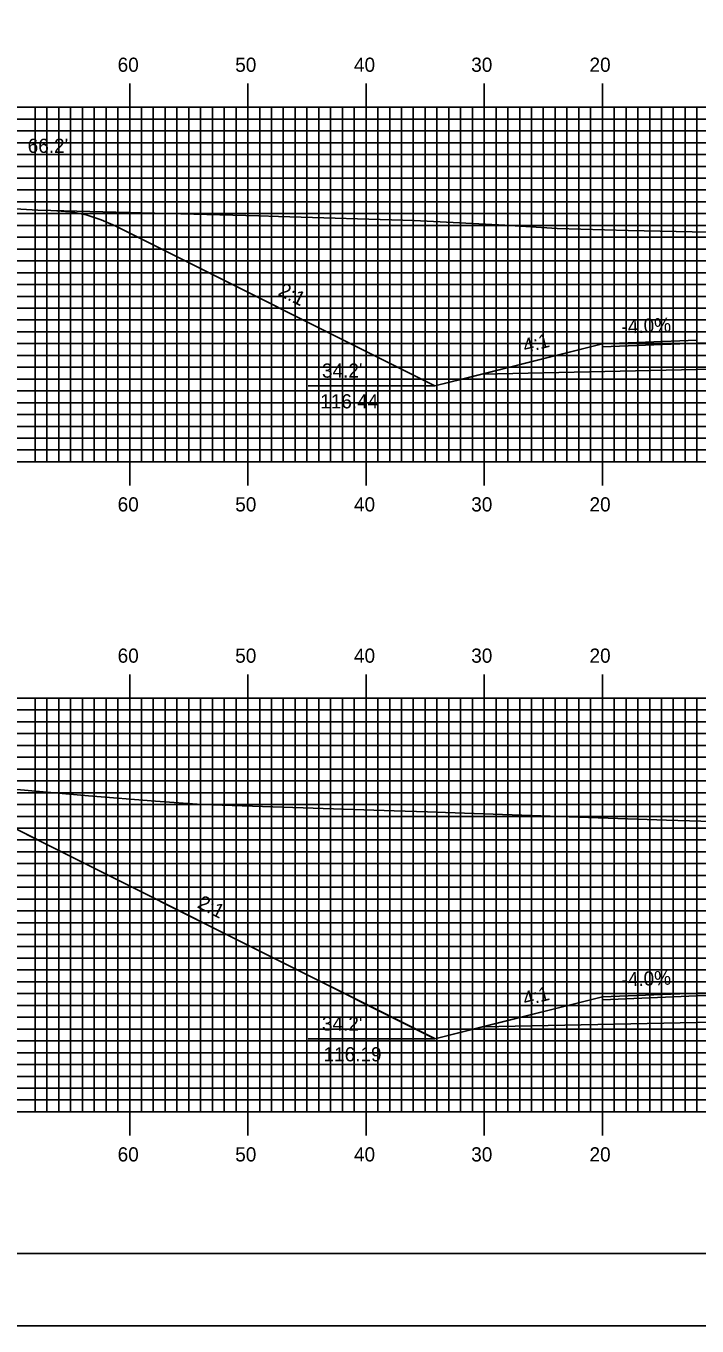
# Model space of a CAD drawing. Extents: x 1770842 to 1771185, y 442591 to 442811.
# Drawn here: x 1770938.8 to 1770995.6, y 442590.5 to 442700.5 of the extents above; entities that cross this region are included whole.
import ezdxf

# ---------------------------------------------------------------- set-up
doc = ezdxf.new("R2010")
doc.units = 0
for name, color, linetype in [('ANNOTATION', 7, 'Continuous'), ('BORDER', 7, 'Continuous'), ('D_Roadway_Centerline', 7, 'Continuous'), ('D_Roadway_Edge_Shoulder', 7, 'Continuous'), ('D_Roadway_SlopeLines', 7, 'Continuous'), ('D_Roadway_SubGrade', 7, 'Continuous'), ('D_Text_Standard', 7, 'Continuous'), ('H_V ANNOTATION', 7, 'Continuous'), ('MAJOR', 7, 'Continuous'), ('MINOR', 7, 'Continuous'), ('PDRAIN', 7, 'Continuous'), ('PLOT BOUNDARY', 7, 'Continuous'), ('S_Roadway_Centerline', 7, 'Continuous')]:
    doc.layers.add(name, color=color, linetype=linetype)

msp = doc.modelspace()

# ---------------------------------------------------------------- linework, layer by layer
at = {"layer": 'BORDER'}
msp.add_lwpolyline([(1770857.95, 442596.67), (1771177.95, 442596.67), (1771177.95, 442806.67), (1770857.95, 442806.67)], close=True, dxfattribs=at)
at = {"layer": 'D_Roadway_Centerline'}
for points in [[(1770941.38, 442684.91), (1770942.49, 442684.82), (1770942.63, 442684.81), (1770942.88, 442684.76), (1770943.88, 442684.56), (1770944.45, 442684.37), (1770945.13, 442684.15), (1770946.32, 442683.63), (1770946.38, 442683.6), (1770946.82, 442683.38), (1770973.38, 442670.1), (1770975.79, 442670.7), (1770977.38, 442671.1), (1770987.55, 442673.65), (1770995.55, 442673.97)], [(1770928.14, 442636.32), (1770928.6, 442636.27), (1770929.39, 442636.2), (1770930.36, 442635.99), (1770930.64, 442635.93), (1770931.48, 442635.66), (1770931.89, 442635.53), (1770933.14, 442634.97), (1770933.14, 442634.97), (1770955.81, 442623.64), (1770973.37, 442614.86), (1770973.38, 442614.85), (1770977.38, 442615.85), (1770977.38, 442615.85), (1770987.55, 442618.4), (1770995.55, 442618.72), (1771007.55, 442618.96), (1771019.55, 442618.72), (1771027.55, 442618.4), (1771027.55, 442618.4), (1771037.73, 442615.85), (1771041.73, 442614.85), (1771041.74, 442614.86), (1771068.97, 442628.47)]]:
    msp.add_lwpolyline(points, dxfattribs=at)
at = {"layer": 'D_Roadway_Edge_Shoulder'}
for points in [[(1770995.55, 442673.97), (1770987.55, 442673.65), (1770987.55, 442673.4), (1770995.55, 442673.72)], [(1770995.55, 442618.72), (1770987.55, 442618.4), (1770987.55, 442618.15), (1770995.55, 442618.47)]]:
    msp.add_lwpolyline(points, close=True, dxfattribs=at)
at = {"layer": 'D_Roadway_SlopeLines'}
for points in [[(1770973.38, 442670.1), (1770946.38, 442683.6), (1770945.13, 442684.15), (1770943.88, 442684.56), (1770942.63, 442684.81), (1770941.38, 442684.91)], [(1770987.55, 442673.65), (1770973.38, 442670.1)], [(1770973.38, 442614.85), (1770933.14, 442634.97), (1770931.89, 442635.53), (1770930.64, 442635.93), (1770929.39, 442636.2), (1770928.14, 442636.32)], [(1770987.55, 442618.4), (1770973.38, 442614.85)]]:
    msp.add_lwpolyline(points, dxfattribs=at)
at = {"layer": 'D_Roadway_SubGrade'}
for points in [[(1770995.55, 442671.47), (1770977.38, 442671.1), (1770987.55, 442673.65), (1770987.55, 442673.4), (1770995.55, 442673.72), (1771007.55, 442673.96), (1771019.55, 442673.72), (1771027.55, 442673.4), (1771027.55, 442673.65), (1771037.73, 442671.1), (1771019.55, 442671.47), (1771007.55, 442671.71)], [(1770995.55, 442616.22), (1770977.38, 442615.85), (1770987.55, 442618.4), (1770987.55, 442618.15), (1770995.55, 442618.47), (1771007.55, 442618.71), (1771019.55, 442618.47), (1771027.55, 442618.15), (1771027.55, 442618.4), (1771037.73, 442615.85), (1771019.55, 442616.22), (1771007.55, 442616.46)]]:
    msp.add_lwpolyline(points, close=True, dxfattribs=at)
at = {"layer": 'MAJOR'}
for p, q in [((1770947.55, 442695.67), (1770947.55, 442693.67)), ((1770957.55, 442695.67), (1770957.55, 442693.67)), ((1770967.55, 442695.67), (1770967.55, 442693.67)), ((1770977.55, 442695.67), (1770977.55, 442693.67)), ((1770987.55, 442695.67), (1770987.55, 442693.67)), ((1770867.55, 442693.67), (1771147.55, 442693.67)), ((1770867.55, 442693.67), (1771147.55, 442693.67)), ((1770947.55, 442663.67), (1770947.55, 442693.67)), ((1770957.55, 442663.67), (1770957.55, 442693.67)), ((1770967.55, 442663.67), (1770967.55, 442693.67)), ((1770977.55, 442663.67), (1770977.55, 442693.67)), ((1770987.55, 442663.67), (1770987.55, 442693.67)), ((1770867.55, 442688.67), (1771147.55, 442688.67)), ((1770867.55, 442683.67), (1771147.55, 442683.67)), ((1770867.55, 442678.67), (1771147.55, 442678.67)), ((1770867.55, 442673.67), (1771147.55, 442673.67)), ((1770867.55, 442668.67), (1771147.55, 442668.67)), ((1770867.55, 442663.67), (1771147.55, 442663.67)), ((1770867.55, 442663.67), (1771147.55, 442663.67)), ((1770947.55, 442661.66), (1770947.55, 442663.67)), ((1770957.55, 442661.66), (1770957.55, 442663.67)), ((1770967.55, 442661.66), (1770967.55, 442663.67)), ((1770977.55, 442661.66), (1770977.55, 442663.67)), ((1770987.55, 442661.66), (1770987.55, 442663.67)), ((1770947.55, 442645.67), (1770947.55, 442643.67)), ((1770957.55, 442645.67), (1770957.55, 442643.67)), ((1770967.55, 442645.67), (1770967.55, 442643.67)), ((1770977.55, 442645.67), (1770977.55, 442643.67)), ((1770987.55, 442645.67), (1770987.55, 442643.67)), ((1770867.55, 442643.67), (1771147.55, 442643.67)), ((1770867.55, 442643.67), (1771147.55, 442643.67)), ((1770947.55, 442608.67), (1770947.55, 442643.67)), ((1770957.55, 442608.67), (1770957.55, 442643.67)), ((1770967.55, 442608.67), (1770967.55, 442643.67)), ((1770977.55, 442608.67), (1770977.55, 442643.67)), ((1770987.55, 442608.67), (1770987.55, 442643.67)), ((1770867.55, 442638.67), (1771147.55, 442638.67)), ((1770867.55, 442633.67), (1771147.55, 442633.67)), ((1770867.55, 442628.67), (1771147.55, 442628.67)), ((1770867.55, 442623.67), (1771147.55, 442623.67)), ((1770867.55, 442618.67), (1771147.55, 442618.67)), ((1770867.55, 442613.67), (1771147.55, 442613.67)), ((1770867.55, 442608.67), (1771147.55, 442608.67)), ((1770867.55, 442608.67), (1771147.55, 442608.67)), ((1770947.55, 442606.66), (1770947.55, 442608.67)), ((1770957.55, 442606.66), (1770957.55, 442608.67)), ((1770967.55, 442606.66), (1770967.55, 442608.67)), ((1770977.55, 442606.66), (1770977.55, 442608.67)), ((1770987.55, 442606.66), (1770987.55, 442608.67))]:
    msp.add_line(p, q, dxfattribs=at)
at = {"layer": 'MINOR'}
for p, q in [((1770939.55, 442663.67), (1770939.55, 442693.67)), ((1770940.55, 442663.67), (1770940.55, 442693.67)), ((1770941.55, 442663.67), (1770941.55, 442693.67)), ((1770942.55, 442663.67), (1770942.55, 442693.67)), ((1770943.55, 442663.67), (1770943.55, 442693.67)), ((1770944.55, 442663.67), (1770944.55, 442693.67)), ((1770945.55, 442663.67), (1770945.55, 442693.67)), ((1770946.55, 442663.67), (1770946.55, 442693.67)), ((1770948.55, 442663.67), (1770948.55, 442693.67)), ((1770949.55, 442663.67), (1770949.55, 442693.67)), ((1770950.55, 442663.67), (1770950.55, 442693.67)), ((1770951.55, 442663.67), (1770951.55, 442693.67)), ((1770952.55, 442663.67), (1770952.55, 442693.67)), ((1770953.55, 442663.67), (1770953.55, 442693.67)), ((1770954.55, 442663.67), (1770954.55, 442693.67)), ((1770955.55, 442663.67), (1770955.55, 442693.67)), ((1770956.55, 442663.67), (1770956.55, 442693.67)), ((1770958.55, 442663.67), (1770958.55, 442693.67)), ((1770959.55, 442663.67), (1770959.55, 442693.67)), ((1770960.55, 442663.67), (1770960.55, 442693.67)), ((1770961.55, 442663.67), (1770961.55, 442693.67)), ((1770962.55, 442663.67), (1770962.55, 442693.67)), ((1770963.55, 442663.67), (1770963.55, 442693.67)), ((1770964.55, 442663.67), (1770964.55, 442693.67)), ((1770965.55, 442663.67), (1770965.55, 442693.67)), ((1770966.55, 442663.67), (1770966.55, 442693.67)), ((1770968.55, 442663.67), (1770968.55, 442693.67)), ((1770969.55, 442663.67), (1770969.55, 442693.67)), ((1770970.55, 442663.67), (1770970.55, 442693.67)), ((1770971.55, 442663.67), (1770971.55, 442693.67)), ((1770972.55, 442663.67), (1770972.55, 442693.67)), ((1770973.55, 442663.67), (1770973.55, 442693.67)), ((1770974.55, 442663.67), (1770974.55, 442693.67)), ((1770975.55, 442663.67), (1770975.55, 442693.67)), ((1770976.55, 442663.67), (1770976.55, 442693.67)), ((1770978.55, 442663.67), (1770978.55, 442693.67)), ((1770979.55, 442663.67), (1770979.55, 442693.67)), ((1770980.55, 442663.67), (1770980.55, 442693.67)), ((1770981.55, 442663.67), (1770981.55, 442693.67)), ((1770982.55, 442663.67), (1770982.55, 442693.67)), ((1770983.55, 442663.67), (1770983.55, 442693.67)), ((1770984.55, 442663.67), (1770984.55, 442693.67)), ((1770985.55, 442663.67), (1770985.55, 442693.67)), ((1770986.55, 442663.67), (1770986.55, 442693.67)), ((1770988.55, 442663.67), (1770988.55, 442693.67)), ((1770989.55, 442663.67), (1770989.55, 442693.67)), ((1770990.55, 442663.67), (1770990.55, 442693.67)), ((1770991.55, 442663.67), (1770991.55, 442693.67)), ((1770992.55, 442663.67), (1770992.55, 442693.67)), ((1770993.55, 442663.67), (1770993.55, 442693.67)), ((1770994.55, 442663.67), (1770994.55, 442693.67)), ((1770995.55, 442663.67), (1770995.55, 442693.67)), ((1770867.55, 442692.67), (1771147.55, 442692.67)), ((1770867.55, 442691.67), (1771147.55, 442691.67)), ((1770867.55, 442690.67), (1771147.55, 442690.67)), ((1770867.55, 442689.67), (1771147.55, 442689.67)), ((1770867.55, 442687.67), (1771147.55, 442687.67)), ((1770867.55, 442686.67), (1771147.55, 442686.67)), ((1770867.55, 442685.67), (1771147.55, 442685.67)), ((1770867.55, 442684.67), (1771147.55, 442684.67)), ((1770867.55, 442682.67), (1771147.55, 442682.67)), ((1770867.55, 442681.67), (1771147.55, 442681.67)), ((1770867.55, 442680.67), (1771147.55, 442680.67)), ((1770867.55, 442679.67), (1771147.55, 442679.67)), ((1770867.55, 442677.67), (1771147.55, 442677.67)), ((1770867.55, 442676.67), (1771147.55, 442676.67)), ((1770867.55, 442675.67), (1771147.55, 442675.67)), ((1770867.55, 442674.67), (1771147.55, 442674.67)), ((1770867.55, 442672.67), (1771147.55, 442672.67)), ((1770867.55, 442671.67), (1771147.55, 442671.67)), ((1770867.55, 442670.67), (1771147.55, 442670.67)), ((1770867.55, 442669.67), (1771147.55, 442669.67)), ((1770867.55, 442667.67), (1771147.55, 442667.67)), ((1770867.55, 442666.67), (1771147.55, 442666.67)), ((1770867.55, 442665.67), (1771147.55, 442665.67)), ((1770867.55, 442664.67), (1771147.55, 442664.67)), ((1770939.55, 442608.67), (1770939.55, 442643.67)), ((1770940.55, 442608.67), (1770940.55, 442643.67)), ((1770941.55, 442608.67), (1770941.55, 442643.67)), ((1770942.55, 442608.67), (1770942.55, 442643.67)), ((1770943.55, 442608.67), (1770943.55, 442643.67)), ((1770944.55, 442608.67), (1770944.55, 442643.67)), ((1770945.55, 442608.67), (1770945.55, 442643.67)), ((1770946.55, 442608.67), (1770946.55, 442643.67)), ((1770948.55, 442608.67), (1770948.55, 442643.67)), ((1770949.55, 442608.67), (1770949.55, 442643.67)), ((1770950.55, 442608.67), (1770950.55, 442643.67)), ((1770951.55, 442608.67), (1770951.55, 442643.67)), ((1770952.55, 442608.67), (1770952.55, 442643.67)), ((1770953.55, 442608.67), (1770953.55, 442643.67)), ((1770954.55, 442608.67), (1770954.55, 442643.67)), ((1770955.55, 442608.67), (1770955.55, 442643.67)), ((1770956.55, 442608.67), (1770956.55, 442643.67)), ((1770958.55, 442608.67), (1770958.55, 442643.67)), ((1770959.55, 442608.67), (1770959.55, 442643.67)), ((1770960.55, 442608.67), (1770960.55, 442643.67)), ((1770961.55, 442608.67), (1770961.55, 442643.67)), ((1770962.55, 442608.67), (1770962.55, 442643.67)), ((1770963.55, 442608.67), (1770963.55, 442643.67)), ((1770964.55, 442608.67), (1770964.55, 442643.67)), ((1770965.55, 442608.67), (1770965.55, 442643.67)), ((1770966.55, 442608.67), (1770966.55, 442643.67)), ((1770968.55, 442608.67), (1770968.55, 442643.67)), ((1770969.55, 442608.67), (1770969.55, 442643.67)), ((1770970.55, 442608.67), (1770970.55, 442643.67)), ((1770971.55, 442608.67), (1770971.55, 442643.67)), ((1770972.55, 442608.67), (1770972.55, 442643.67)), ((1770973.55, 442608.67), (1770973.55, 442643.67)), ((1770974.55, 442608.67), (1770974.55, 442643.67)), ((1770975.55, 442608.67), (1770975.55, 442643.67)), ((1770976.55, 442608.67), (1770976.55, 442643.67)), ((1770978.55, 442608.67), (1770978.55, 442643.67)), ((1770979.55, 442608.67), (1770979.55, 442643.67)), ((1770980.55, 442608.67), (1770980.55, 442643.67)), ((1770981.55, 442608.67), (1770981.55, 442643.67)), ((1770982.55, 442608.67), (1770982.55, 442643.67)), ((1770983.55, 442608.67), (1770983.55, 442643.67)), ((1770984.55, 442608.67), (1770984.55, 442643.67)), ((1770985.55, 442608.67), (1770985.55, 442643.67)), ((1770986.55, 442608.67), (1770986.55, 442643.67)), ((1770988.55, 442608.67), (1770988.55, 442643.67)), ((1770989.55, 442608.67), (1770989.55, 442643.67)), ((1770990.55, 442608.67), (1770990.55, 442643.67)), ((1770991.55, 442608.67), (1770991.55, 442643.67)), ((1770992.55, 442608.67), (1770992.55, 442643.67)), ((1770993.55, 442608.67), (1770993.55, 442643.67)), ((1770994.55, 442608.67), (1770994.55, 442643.67)), ((1770995.55, 442608.67), (1770995.55, 442643.67)), ((1770867.55, 442642.67), (1771147.55, 442642.67)), ((1770867.55, 442641.67), (1771147.55, 442641.67)), ((1770867.55, 442640.67), (1771147.55, 442640.67)), ((1770867.55, 442639.67), (1771147.55, 442639.67)), ((1770867.55, 442637.67), (1771147.55, 442637.67)), ((1770867.55, 442636.67), (1771147.55, 442636.67)), ((1770867.55, 442635.67), (1771147.55, 442635.67)), ((1770867.55, 442634.67), (1771147.55, 442634.67)), ((1770867.55, 442632.67), (1771147.55, 442632.67)), ((1770867.55, 442631.67), (1771147.55, 442631.67)), ((1770867.55, 442630.67), (1771147.55, 442630.67)), ((1770867.55, 442629.67), (1771147.55, 442629.67)), ((1770867.55, 442627.67), (1771147.55, 442627.67)), ((1770867.55, 442626.67), (1771147.55, 442626.67)), ((1770867.55, 442625.67), (1771147.55, 442625.67)), ((1770867.55, 442624.67), (1771147.55, 442624.67)), ((1770867.55, 442622.67), (1771147.55, 442622.67)), ((1770867.55, 442621.67), (1771147.55, 442621.67)), ((1770867.55, 442620.67), (1771147.55, 442620.67)), ((1770867.55, 442619.67), (1771147.55, 442619.67)), ((1770867.55, 442617.67), (1771147.55, 442617.67)), ((1770867.55, 442616.67), (1771147.55, 442616.67)), ((1770867.55, 442615.67), (1771147.55, 442615.67)), ((1770867.55, 442614.67), (1771147.55, 442614.67)), ((1770867.55, 442612.67), (1771147.55, 442612.67)), ((1770867.55, 442611.67), (1771147.55, 442611.67)), ((1770867.55, 442610.67), (1771147.55, 442610.67)), ((1770867.55, 442609.67), (1771147.55, 442609.67))]:
    msp.add_line(p, q, dxfattribs=at)
at = {"layer": 'PDRAIN'}
for p, q in [((1770962.66, 442670.1), (1770973.38, 442670.1)), ((1770962.66, 442614.85), (1770973.38, 442614.85))]:
    msp.add_line(p, q, dxfattribs=at)
at = {"layer": 'PLOT BOUNDARY'}
msp.add_lwpolyline([(1770841.77, 442590.55), (1771181.77, 442590.55), (1771181.77, 442810.55), (1770841.77, 442810.55)], close=True, dxfattribs=at)
at = {"layer": 'S_Roadway_Centerline'}
for points in [[(1770930.09, 442685.53), (1770939.79, 442684.95), (1770958.47, 442684.49), (1770960.13, 442684.42), (1770971.63, 442684.09), (1770979.3, 442683.69), (1770983.73, 442683.41), (1770989.74, 442683.24), (1770999.2, 442683.04), (1771017.78, 442682.3), (1771018.44, 442682.27), (1771018.58, 442682.27), (1771018.81, 442682.25), (1771030.84, 442681.26), (1771038.66, 442680.87), (1771042.63, 442680.75), (1771047.93, 442680.53), (1771065.88, 442679.27)], [(1770937.99, 442635.94), (1770944.06, 442635.42), (1770949.74, 442634.96), (1770953.65, 442634.66), (1770969.93, 442634.14), (1770972.75, 442634.05), (1770974.28, 442634), (1770985.56, 442633.61), (1770992.98, 442633.36), (1771003.62, 442633.05), (1771013.38, 442632.73), (1771029.95, 442632.11), (1771032.3, 442632.02), (1771033.55, 442631.96), (1771051.78, 442630.64), (1771056.29, 442630.34), (1771061.87, 442630), (1771072.36, 442629.7)]]:
    msp.add_lwpolyline(points, dxfattribs=at)

# ---------------------------------------------------------------- texts
at = {"layer": 'ANNOTATION'}
for s, rotation, p in [('2:1', 333.4343, (1770960.03, 442677.81)), ('-4.0%', 2.2906, (1770989.19, 442674.51)), ('4:1', 14.0387, (1770981, 442672.87)), ('2:1', 333.4352, (1770953.19, 442625.98)), ('-4.0%', 2.2906, (1770989.19, 442619.26)), ('4:1', 14.0396, (1770981, 442617.62))]:
    msp.add_text(s, height=1.2, rotation=rotation, dxfattribs=at).set_placement(p)
for s, p in [("34.2'", (1770963.82, 442670.79)), ('116.44', (1770963.67, 442668.19)), ("34.2'", (1770963.82, 442615.54)), ('116.19', (1770963.95, 442612.94))]:
    msp.add_text(s, height=1.2, dxfattribs=at).set_placement(p)
at = {"layer": 'D_Text_Standard'}
msp.add_text("66.2'", height=1.2, dxfattribs=at).set_placement((1770938.92, 442689.81))
at = {"layer": 'H_V ANNOTATION'}
for s, p in [('60', (1770946.53, 442696.67)), ('50', (1770956.48, 442696.67)), ('40', (1770966.53, 442696.67)), ('30', (1770976.45, 442696.67)), ('20', (1770986.46, 442696.67)), ('60', (1770946.53, 442659.47)), ('50', (1770956.48, 442659.47)), ('40', (1770966.53, 442659.47)), ('30', (1770976.45, 442659.47)), ('20', (1770986.46, 442659.47)), ('60', (1770946.53, 442646.67)), ('50', (1770956.48, 442646.67)), ('40', (1770966.53, 442646.67)), ('30', (1770976.45, 442646.67)), ('20', (1770986.46, 442646.67)), ('60', (1770946.53, 442604.47)), ('50', (1770956.48, 442604.47)), ('40', (1770966.53, 442604.47)), ('30', (1770976.45, 442604.47)), ('20', (1770986.46, 442604.47))]:
    msp.add_text(s, height=1.2, dxfattribs=at).set_placement(p)

doc.saveas('drawing.dxf')
